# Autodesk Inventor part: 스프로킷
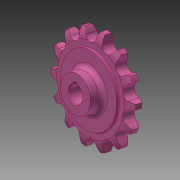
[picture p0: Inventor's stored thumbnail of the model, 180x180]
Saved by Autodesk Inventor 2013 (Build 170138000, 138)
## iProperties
Created: 2016-03
Part Number: 스프로킷
Material: 강철, 탄소
Document SubType Name: Modeling
Designer: mduedu
Density: 7.87 g/cm^3
Mass: 230.696 g
Surface Area: 96.4947 cm^2
Volume: 29.3133 cm^3
Author: mduedu
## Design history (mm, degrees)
sketch "스케치1"
  geometry: L1 (0, 5)-(25, 5); L2 (25, 5)-(25, 4.1); L3 (25.5, 3.6)-(29.125, 3.6); L4 (35.5, 2)-(35.5, 0); L5 (35.5, 0)-(0, 0); L6 (0, 0)-(0, 5); L7 (0, -5)-(25, -5); L8 (25, -5)-(25, -4.1); L9 (25.5, -3.6)-(29.125, -3.6); L10 (35.5, -2)-(35.5, 0); L11 (0, 0)-(0, -5); A1 r 13.5 centre (29.125, -9.9) between (35.5, 2) and (29.125, 3.6); A2 r 13.5 centre (29.125, 9.9) between (29.125, -3.6) and (35.5, -2); A3 r 0.5 centre (25.5, 4.1) between (25, 4.1) and (25.5, 3.6); A4 r 0.5 centre (25.5, -4.1) between (25.5, -3.6) and (25, -4.1); 2 further points
  constraints: 22 end point, 8 point on circle, 6 symmetric about line, 5 tangent, 4 centre point, 4 parallel, 4 point on line, 1 equal radius, 1 horizontal, 1 perpendicular, 1 other
  dimensions: "d0" = 71 diameter of L4 L6; "d2" = 50 diameter of L2 L6; "d3" = 1.6 vertical distance of L4.start L3.end; "d4" = 3.6 distance from line of L4.end L3; "d5" = 5 distance between parallel lines of L5 L1; "d6" = 13.5 radius of A1; "d15" = 0.5 radius of A3
revolve "회전1" sketch "스케치1" stored, may be unused: angle "d7" = 90 deg
sketch "스케치2" dims "d8" = 57.16, "d11" = 71
  geometry: L1 (0, 0)-(0, 28.58); A1 r 32.55 centre (0, 0) between (-16.114, 28.281) and (0, 32.55); A2 r 3.97 centre (0, 32.55) between (-3.838, 31.533) and (0, 28.58); A3 r 12.7 centre (-16.114, 28.281) between (-3.838, 31.533) and (-5.392, 35.088); A4 r 12.7 centre (16.114, 28.281) between (5.392, 35.088) and (3.838, 31.533); A5 r 3.97 centre (0, 32.55) between (0, 28.58) and (3.838, 31.533); A6 r 35.5 centre (0, 0) between (5.392, 35.088) and (-5.392, 35.088); 2 further points
  constraints: 12 point on circle, 6 centre point, 4 coincident, 3 symmetric about line, 2 end point, 1 point on line, 1 tangent, 1 vertical, 1 vertical alignment, 7 other
  dimensions: "d10" = 65.1 diameter of A1; "d12" = 12.7 radius of A3
extrude "돌출1" cut sketch "스케치2" stored distance "d13" = 10; taper "d14" = 0 deg
sketch "스케치3"
  geometry: C1 r 11 at (0, 0); 1 further point
  constraints: 1 centre point, 1 coincident
  dimensions: "d19" = 22 diameter of C1
extrude "돌출2" join sketch "스케치3" distance "d20" = 8; taper "d21" = 0 deg
fillet "모깎기1" dims "d22" = 3
sketch "스케치4"
  geometry: L1 (-1.5, 0)-(1.5, 0); L2 (1.5, 0)-(1.5, 6.4); L3 (1.5, 6.4)-(-1.5, 6.4); L4 (-1.5, 6.4)-(-1.5, 0); C1 r 5 at (0, 0); 2 further points
  constraints: 8 end point, 2 coincident, 2 parallel, 1 centre point, 1 horizontal, 1 midpoint, 1 perpendicular
  dimensions: "d23" = 10 diameter of C1; "d25" = 3 distance of L2.end L3.end; "d26" = 6.4 distance of L1.end L2.end
extrude "돌출3" cut sketch "스케치4" stored distance "d27" = 8; taper "d28" = 0 deg
chamfer "모따기1" distance "d29" = 0.5; stored, may be unused: second distance "d30" = 2, angle "d31" = 45 deg
node "솔리드1"
pattern_circular "원형 패턴1" dims angle "d17" = 360 deg
